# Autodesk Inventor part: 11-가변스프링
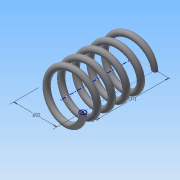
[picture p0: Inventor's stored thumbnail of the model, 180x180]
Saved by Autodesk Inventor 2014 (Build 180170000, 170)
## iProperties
Created: 2015-09
Part Number: 11-가변스프링
Material: 강철, 탄소
Document SubType Name: Modeling
Designer: study
Density: 7.87 g/cm^3
Appearance: 반연마
Mass: 18.8452 g
Surface Area: 32.5051 cm^2
Volume: 2.39456 cm^3
Author: study
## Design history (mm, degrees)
sketch "스케치1"
  geometry: L1 (0, 0)-(11, 0); L2 (11, 0)-(11, 32.877); L3 (11, 32.877)-(0, 32.877); L4 (0, 32.877)-(0, 0); C1 r 1.5 at (11, 0); 1 further point
  constraints: 8 end point, 2 coincident, 2 parallel, 1 centre point, 1 horizontal, 1 perpendicular
  dimensions: "d0" = 22 diameter of L2 L4; "d1" = 32.8769 distance between parallel lines of L1 L3 (derived); "d2" = 3 diameter of C1
feature "코일1" sketch "스케치1" pitch "d3" = 10; turns "d5" = 5; dims "d4" = 32.8769 (= d1), "d6" = 0, angle "d7" = 90 deg, angle "d8" = 90 deg, "d9" = 0, "d10" = 0
node "작업 평면1"
sketch "스케치2"
  geometry: L1 (-12.5, 0)-(-9.5, 0) reference; 1 further point
  constraints: 1 horizontal alignment
extrude "돌출1" cut sketch "스케치2" stored distance "d12" = 10; taper "d13" = 0 deg
node "작업 평면2"
sketch "스케치3"
  geometry: L1 (-9.5, 0)-(-12.5, 0) reference; 1 further point
  constraints: 1 horizontal alignment
extrude "돌출2" cut sketch "스케치3" stored distance "d15" = 10; taper "d16" = 0 deg
node "솔리드1"
node "절단 모서리 투영1"
node "절단 모서리 투영2"
other parameters: "d11" = 0, "d14" = 32.8769 (= d1)
